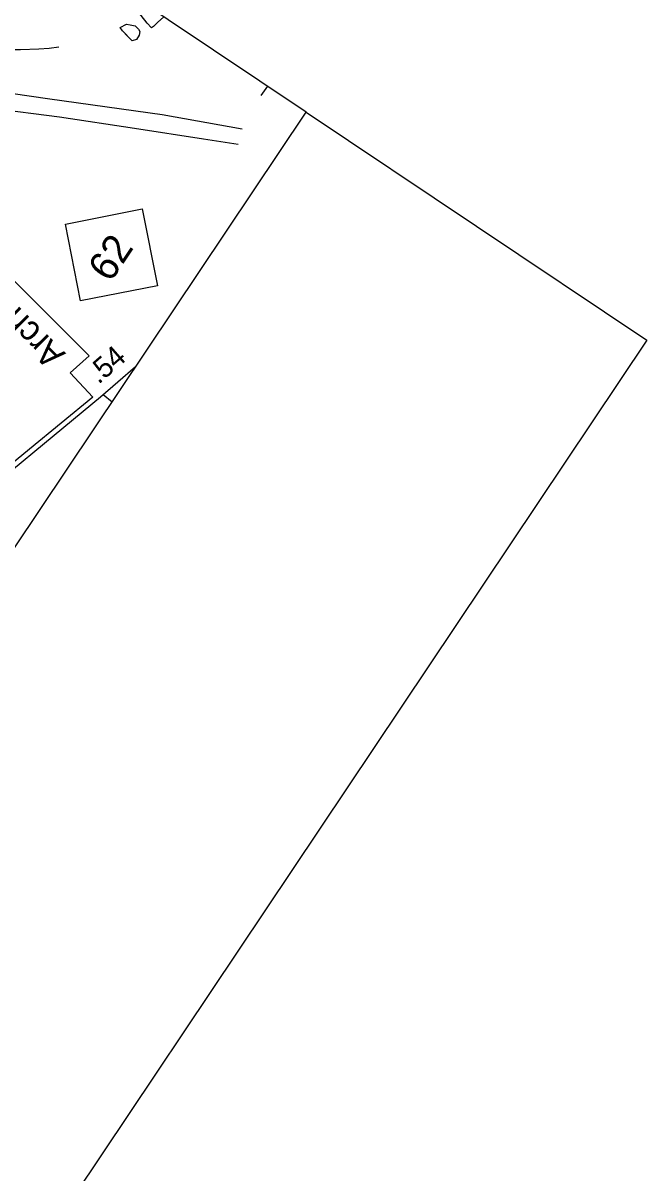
# Model space of a CAD drawing. Extents: x 1715610 to 1720914, y 798298 to 802505.
# Drawn here: x 1716213.5 to 1716295.1, y 799554.8 to 799705.3 of the extents above; entities that cross this region are included whole.
import ezdxf

# ---------------------------------------------------------------- set-up
doc = ezdxf.new("R2010")
doc.units = 0
doc.layers.add('Default', color=7, linetype='Continuous')
doc.layers.add('Prop DSN Text', color=7, linetype='Continuous')

msp = doc.modelspace()

# ---------------------------------------------------------------- linework, layer by layer
at = {"layer": 'Default'}
for points in [[(1716231.91, 799706.12), (1716231.09, 799705.4), (1716230.56, 799704.86), (1716230.28, 799704.69), (1716229.7, 799705.3), (1716228.95, 799706.29), (1716228.25, 799707.18), (1716227.5, 799708.01), (1716227.24, 799708.34)], [(1716231.91, 799706.12), (1716231.09, 799705.4), (1716230.56, 799704.86), (1716230.28, 799704.69), (1716229.7, 799705.3), (1716228.95, 799706.29), (1716228.25, 799707.18), (1716227.24, 799708.34)], [(1716226.17, 799704.76), (1716227.03, 799705.17), (1716227.51, 799705.1), (1716228.14, 799704.94), (1716228.59, 799704.53), (1716228.74, 799704.21), (1716228.68, 799703.73), (1716228.31, 799703.19), (1716227.75, 799702.99), (1716227.2, 799703.58), (1716226.5, 799704.32), (1716226.17, 799704.76)], [(1716226.17, 799704.76), (1716227.03, 799705.17), (1716227.51, 799705.1), (1716228.14, 799704.94), (1716228.59, 799704.53), (1716228.74, 799704.21), (1716228.68, 799703.73), (1716228.31, 799703.19), (1716227.75, 799702.99), (1716226.5, 799704.32), (1716226.17, 799704.76)], [(1716182.38, 799700.37), (1716184.17, 799700.67), (1716186.65, 799701.14), (1716188.64, 799701.57), (1716189.94, 799701.79), (1716191.66, 799701.98), (1716193.24, 799702.22), (1716194.52, 799702.55), (1716195.74, 799702.72), (1716197.24, 799702.75), (1716198.9, 799702.78), (1716206.76, 799702.42), (1716208.08, 799702.26), (1716210.01, 799701.93), (1716211.65, 799701.87), (1716213.13, 799701.86), (1716215.55, 799701.94), (1716216.88, 799702.04), (1716218.16, 799702.22)], [(1716209.45, 799696.49), (1716216.99, 799695.42), (1716231.7, 799693.33), (1716242.17, 799691.48)], [(1716245.45, 799697.05), (1716244.6, 799695.82)], [(1716202.32, 799694.77), (1716209.35, 799694.18), (1716218.23, 799693.05), (1716228.08, 799691.58), (1716237.07, 799690.17), (1716241.61, 799689.45)], [(1716199.6, 799684.2), (1716222.13, 799661.74), (1716219.64, 799659.53), (1716222.61, 799656.33), (1716214.3, 799649.54), (1716208.55, 799644.84), (1716203.57, 799648.81), (1716206.64, 799652.85), (1716194.64, 799666.64), (1716195.14, 799666.93), (1716192.83, 799669.59), (1716191.76, 799670.83), (1716190.1, 799669.81), (1716188.28, 799674.51), (1716197.61, 799686.2), (1716199.6, 799684.2)], [(1716199.6, 799684.2), (1716222.13, 799661.74), (1716219.64, 799659.53), (1716222.61, 799656.33), (1716214.3, 799649.54), (1716208.55, 799644.84), (1716203.57, 799648.81), (1716206.64, 799652.85), (1716194.64, 799666.64), (1716195.14, 799666.93), (1716192.83, 799669.59), (1716191.76, 799670.83), (1716190.1, 799669.81), (1716188.28, 799674.51), (1716197.61, 799686.2), (1716199.6, 799684.2)], [(1716195.65, 799633.35), (1716199.38, 799636.43), (1716202.79, 799639.24), (1716207.59, 799643.18), (1716216.27, 799650.3), (1716223.63, 799656.37), (1716225.89, 799658.37), (1716228.19, 799660.37), (1716228.32, 799660.5)], [(1716223.95, 799656.7), (1716225.13, 799655.74)]]:
    msp.add_lwpolyline(points, dxfattribs=at)
msp.add_lwpolyline([(1716221.01, 799668.95), (1716219.02, 799678.99), (1716229.07, 799680.98), (1716231.06, 799670.94)], close=True, dxfattribs=at)
at = {"layer": 'Prop DSN Text'}
for points in [[(1715972.32, 799278.02), (1716250.51, 799693.66), (1715888.23, 799936.14), (1715610.03, 799520.5)], [(1715972.32, 799278.02), (1716250.51, 799693.66), (1716295.13, 799663.8), (1716016.93, 799248.16)]]:
    msp.add_lwpolyline(points, close=True, dxfattribs=at)

# ---------------------------------------------------------------- texts
at = {"layer": 'Default'}
for s, height, rotation, p in [('Archdale CL', 3.2625, 135.2015, (1716219.14, 799662.06)), ('62', 3.806, 56.2051, (1716224.9, 799671.24)), ('.54', 2.719, 41.1366, (1716223.35, 799657.95))]:
    msp.add_text(s, height=height, rotation=rotation, dxfattribs=at).set_placement(p)

doc.saveas('drawing.dxf')
